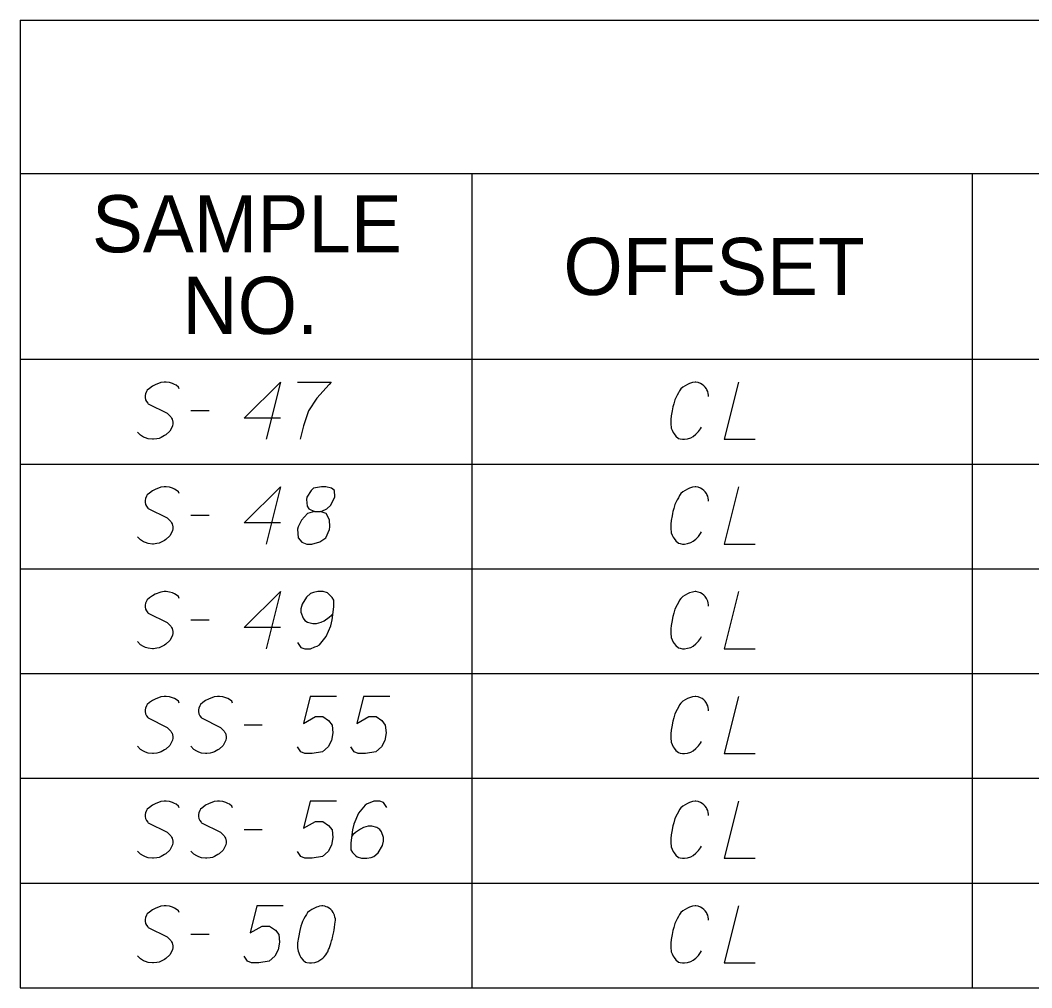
# Model space of a CAD drawing. Extents: x 2074207 to 2076812, y 516372 to 523312.
# Drawn here: x 2076260.6 to 2076345.6, y 517707.2 to 517788.5 of the extents above; entities that cross this region are included whole.
import ezdxf

# ---------------------------------------------------------------- set-up
doc = ezdxf.new("R2010")
doc.units = 0
for name, color, linetype in [('Prop DirtTable_ Soil Test Results - Outline (Major)', 7, 'Continuous'), ('Prop DirtTable_ Soil Test Results - Outline (Minor)', 7, 'Continuous'), ('Prop DirtTable_ Soil Test Results - Tx (Header - Small)', 7, 'Continuous'), ('Prop DirtTable_ Soil Test Results - Tx (Sample Data)', 7, 'Continuous')]:
    doc.layers.add(name, color=color, linetype=linetype)

msp = doc.modelspace()

# ---------------------------------------------------------------- linework, layer by layer
at = {"layer": 'Prop DirtTable_ Soil Test Results - Outline (Major)'}
for p, q in [((2076260.609, 517788.499), (2076260.609, 517760.014)), ((2076260.609, 517788.499), (2076811.903, 517788.499)), ((2076260.609, 517760.014), (2076260.609, 517751.214)), ((2076260.609, 517760.014), (2076811.903, 517760.014)), ((2076260.609, 517760.014), (2076811.903, 517760.014)), ((2076260.609, 517751.214), (2076260.609, 517742.414)), ((2076260.609, 517742.414), (2076260.609, 517733.614)), ((2076260.609, 517733.614), (2076260.609, 517724.814)), ((2076260.609, 517724.814), (2076260.609, 517716.014)), ((2076260.609, 517716.014), (2076260.609, 517707.214)), ((2076260.609, 517707.214), (2076811.903, 517707.214))]:
    msp.add_line(p, q, dxfattribs=at)
at = {"layer": 'Prop DirtTable_ Soil Test Results - Outline (Minor)'}
for p, q in [((2076260.609, 517775.614), (2076811.903, 517775.614)), ((2076298.545, 517775.614), (2076298.545, 517751.214)), ((2076340.594, 517775.614), (2076340.594, 517751.214)), ((2076260.609, 517751.214), (2076811.903, 517751.214)), ((2076260.609, 517751.214), (2076811.903, 517751.214)), ((2076298.546, 517751.214), (2076298.546, 517742.414)), ((2076340.594, 517751.214), (2076340.594, 517742.414)), ((2076260.609, 517742.414), (2076811.903, 517742.414)), ((2076260.609, 517742.414), (2076811.903, 517742.414)), ((2076298.546, 517742.414), (2076298.546, 517733.614)), ((2076340.594, 517742.414), (2076340.594, 517733.614)), ((2076260.609, 517733.614), (2076811.903, 517733.614)), ((2076260.609, 517733.614), (2076811.903, 517733.614)), ((2076298.546, 517733.614), (2076298.546, 517724.814)), ((2076340.594, 517733.614), (2076340.594, 517724.814)), ((2076260.609, 517724.814), (2076811.903, 517724.814)), ((2076260.609, 517724.814), (2076811.903, 517724.814)), ((2076298.546, 517724.814), (2076298.546, 517716.014)), ((2076340.594, 517724.814), (2076340.594, 517716.014)), ((2076260.609, 517716.014), (2076811.903, 517716.014)), ((2076260.609, 517716.014), (2076811.903, 517716.014)), ((2076298.546, 517716.014), (2076298.546, 517707.214)), ((2076340.594, 517716.014), (2076340.594, 517707.214)), ((2076260.609, 517707.214), (2076811.903, 517707.214))]:
    msp.add_line(p, q, dxfattribs=at)
at = {"layer": 'Prop DirtTable_ Soil Test Results - Tx (Sample Data)'}
for points in [[(2076273.968, 517757.528), (2076273.897, 517757.68), (2076273.721, 517757.831), (2076273.58, 517757.906), (2076273.403, 517757.982), (2076273.157, 517758.058), (2076272.874, 517758.095), (2076272.698, 517758.095), (2076272.416, 517758.058), (2076271.957, 517757.869), (2076271.71, 517757.755), (2076271.463, 517757.566), (2076271.287, 517757.415), (2076271.216, 517757.302), (2076271.146, 517757.113), (2076271.111, 517756.961), (2076271.111, 517756.81), (2076271.146, 517756.621), (2076271.216, 517756.47), (2076271.322, 517756.319), (2076271.358, 517756.281), (2076272.945, 517755.487), (2076273.262, 517755.185), (2076273.333, 517755.072), (2076273.368, 517754.996), (2076273.439, 517754.732), (2076273.439, 517754.58), (2076273.403, 517754.429), (2076273.333, 517754.24), (2076273.192, 517753.976), (2076272.839, 517753.673), (2076272.733, 517753.598), (2076272.451, 517753.446), (2076272.275, 517753.371), (2076272.098, 517753.333), (2076271.816, 517753.295), (2076271.71, 517753.295), (2076271.358, 517753.333), (2076271.146, 517753.409), (2076270.969, 517753.484), (2076270.723, 517753.635), (2076270.476, 517753.9)], [(2076282.469, 517755.072), (2076279.436, 517755.072), (2076282.469, 517758.095), (2076281.27, 517753.295)], [(2076283.916, 517758.095), (2076286.738, 517758.095), (2076286.561, 517757.906), (2076285.538, 517756.735), (2076284.833, 517755.676), (2076284.409, 517754.429), (2076284.127, 517753.295)], [(2076318.45, 517756.886), (2076318.45, 517756.999), (2076318.415, 517757.15), (2076318.38, 517757.302), (2076318.309, 517757.453), (2076318.274, 517757.528), (2076318.168, 517757.68), (2076318.062, 517757.793), (2076317.921, 517757.906), (2076317.78, 517757.982), (2076317.569, 517758.058), (2076317.392, 517758.095), (2076317.322, 517758.095), (2076317.11, 517758.058), (2076316.863, 517757.982), (2076316.687, 517757.906), (2076316.475, 517757.793), (2076316.299, 517757.68), (2076316.122, 517757.528), (2076316.016, 517757.377), (2076315.911, 517757.188), (2076315.805, 517756.999), (2076315.628, 517756.621), (2076315.523, 517756.281), (2076315.452, 517756.017), (2076315.417, 517755.865), (2076315.381, 517755.676), (2076315.311, 517755.261), (2076315.276, 517754.958), (2076315.276, 517754.618), (2076315.311, 517754.24), (2076315.381, 517754.051), (2076315.487, 517753.862), (2076315.558, 517753.749), (2076315.699, 517753.56), (2076315.911, 517753.371), (2076316.052, 517753.333), (2076316.263, 517753.295), (2076316.404, 517753.295), (2076316.44, 517753.295), (2076316.687, 517753.333), (2076316.969, 517753.409), (2076317.145, 517753.522), (2076317.392, 517753.711), (2076317.604, 517753.938), (2076317.78, 517754.165), (2076317.851, 517754.316)], [(2076320.955, 517758.095), (2076319.756, 517753.295), (2076322.366, 517753.295)], [(2076274.956, 517755.714), (2076276.472, 517755.714)], [(2076273.968, 517748.728), (2076273.897, 517748.88), (2076273.721, 517749.031), (2076273.58, 517749.106), (2076273.403, 517749.182), (2076273.157, 517749.258), (2076272.874, 517749.295), (2076272.698, 517749.295), (2076272.416, 517749.258), (2076271.957, 517749.069), (2076271.71, 517748.955), (2076271.463, 517748.766), (2076271.287, 517748.615), (2076271.216, 517748.502), (2076271.146, 517748.313), (2076271.111, 517748.161), (2076271.111, 517748.01), (2076271.146, 517747.821), (2076271.216, 517747.67), (2076271.322, 517747.519), (2076271.358, 517747.481), (2076272.945, 517746.687), (2076273.262, 517746.385), (2076273.333, 517746.272), (2076273.368, 517746.196), (2076273.439, 517745.932), (2076273.439, 517745.78), (2076273.403, 517745.629), (2076273.333, 517745.44), (2076273.192, 517745.176), (2076272.839, 517744.873), (2076272.733, 517744.798), (2076272.451, 517744.646), (2076272.275, 517744.571), (2076272.098, 517744.533), (2076271.816, 517744.495), (2076271.71, 517744.495), (2076271.358, 517744.533), (2076271.146, 517744.609), (2076270.969, 517744.684), (2076270.723, 517744.835), (2076270.476, 517745.1)], [(2076282.469, 517746.272), (2076279.436, 517746.272), (2076282.469, 517749.295), (2076281.27, 517744.495)], [(2076285.327, 517747.217), (2076285.82, 517747.217), (2076285.962, 517747.254), (2076286.385, 517747.443), (2076286.702, 517747.746), (2076287.055, 517748.464), (2076287.02, 517748.993), (2076286.773, 517749.182), (2076286.279, 517749.295), (2076285.926, 517749.295), (2076285.256, 517749.182), (2076285.044, 517748.993), (2076284.692, 517748.426), (2076284.656, 517748.237), (2076284.727, 517747.67), (2076284.868, 517747.443), (2076285.327, 517747.217), (2076284.762, 517747.065), (2076284.233, 517746.498), (2076283.951, 517745.932), (2076283.916, 517745.743), (2076283.951, 517745.024), (2076284.268, 517744.646), (2076284.692, 517744.495), (2076285.115, 517744.495), (2076285.785, 517744.684), (2076286.279, 517745.024), (2076286.597, 517745.705), (2076286.632, 517745.932), (2076286.597, 517746.536), (2076286.314, 517747.065), (2076285.82, 517747.217)], [(2076318.45, 517748.086), (2076318.45, 517748.199), (2076318.415, 517748.35), (2076318.38, 517748.502), (2076318.309, 517748.653), (2076318.274, 517748.728), (2076318.168, 517748.88), (2076318.062, 517748.993), (2076317.921, 517749.106), (2076317.78, 517749.182), (2076317.569, 517749.258), (2076317.392, 517749.295), (2076317.322, 517749.295), (2076317.11, 517749.258), (2076316.863, 517749.182), (2076316.687, 517749.106), (2076316.475, 517748.993), (2076316.299, 517748.88), (2076316.122, 517748.728), (2076316.016, 517748.577), (2076315.911, 517748.388), (2076315.805, 517748.199), (2076315.628, 517747.821), (2076315.523, 517747.481), (2076315.452, 517747.217), (2076315.417, 517747.065), (2076315.381, 517746.876), (2076315.311, 517746.461), (2076315.276, 517746.158), (2076315.276, 517745.818), (2076315.311, 517745.44), (2076315.381, 517745.251), (2076315.487, 517745.062), (2076315.558, 517744.949), (2076315.699, 517744.76), (2076315.911, 517744.571), (2076316.052, 517744.533), (2076316.263, 517744.495), (2076316.404, 517744.495), (2076316.44, 517744.495), (2076316.687, 517744.533), (2076316.969, 517744.609), (2076317.145, 517744.722), (2076317.392, 517744.911), (2076317.604, 517745.138), (2076317.78, 517745.365), (2076317.851, 517745.516)], [(2076320.955, 517749.295), (2076319.756, 517744.495), (2076322.366, 517744.495)], [(2076274.956, 517746.914), (2076276.472, 517746.914)], [(2076273.968, 517739.928), (2076273.897, 517740.08), (2076273.721, 517740.231), (2076273.58, 517740.306), (2076273.403, 517740.382), (2076273.157, 517740.458), (2076272.874, 517740.495), (2076272.698, 517740.495), (2076272.416, 517740.458), (2076271.957, 517740.269), (2076271.71, 517740.155), (2076271.463, 517739.966), (2076271.287, 517739.815), (2076271.216, 517739.702), (2076271.146, 517739.513), (2076271.111, 517739.361), (2076271.111, 517739.21), (2076271.146, 517739.021), (2076271.216, 517738.87), (2076271.322, 517738.719), (2076271.358, 517738.681), (2076272.945, 517737.887), (2076273.262, 517737.585), (2076273.333, 517737.472), (2076273.368, 517737.396), (2076273.439, 517737.132), (2076273.439, 517736.98), (2076273.403, 517736.829), (2076273.333, 517736.64), (2076273.192, 517736.376), (2076272.839, 517736.073), (2076272.733, 517735.998), (2076272.451, 517735.846), (2076272.275, 517735.771), (2076272.098, 517735.733), (2076271.816, 517735.695), (2076271.71, 517735.695), (2076271.358, 517735.733), (2076271.146, 517735.809), (2076270.969, 517735.884), (2076270.723, 517736.035), (2076270.476, 517736.3)], [(2076282.469, 517737.472), (2076279.436, 517737.472), (2076282.469, 517740.495), (2076281.27, 517735.695)], [(2076283.916, 517736.224), (2076284.198, 517735.809), (2076284.515, 517735.695), (2076285.009, 517735.695), (2076285.362, 517735.846), (2076285.574, 517735.922), (2076285.75, 517736.035), (2076286.314, 517736.716), (2076286.702, 517737.623), (2076286.808, 517738.114), (2076286.949, 517739.21), (2076286.949, 517739.777), (2076286.808, 517740.004), (2076286.526, 517740.306), (2076286.42, 517740.382), (2076286.067, 517740.495), (2076285.609, 517740.495), (2076285.256, 517740.42), (2076285.009, 517740.344), (2076284.656, 517740.042), (2076284.304, 517739.437), (2076284.198, 517739.059), (2076284.198, 517738.757), (2076284.374, 517738.265), (2076284.515, 517738.076), (2076284.762, 517737.925), (2076285.186, 517737.812), (2076285.503, 517737.812), (2076285.891, 517737.925), (2076286.138, 517738.039), (2076286.561, 517738.341), (2076286.773, 517738.53), (2076286.879, 517738.643)], [(2076318.45, 517739.286), (2076318.45, 517739.399), (2076318.415, 517739.55), (2076318.38, 517739.702), (2076318.309, 517739.853), (2076318.274, 517739.928), (2076318.168, 517740.08), (2076318.062, 517740.193), (2076317.921, 517740.306), (2076317.78, 517740.382), (2076317.569, 517740.458), (2076317.392, 517740.495), (2076317.322, 517740.495), (2076317.11, 517740.458), (2076316.863, 517740.382), (2076316.687, 517740.306), (2076316.475, 517740.193), (2076316.299, 517740.08), (2076316.122, 517739.928), (2076316.016, 517739.777), (2076315.911, 517739.588), (2076315.805, 517739.399), (2076315.628, 517739.021), (2076315.523, 517738.681), (2076315.452, 517738.417), (2076315.417, 517738.265), (2076315.381, 517738.076), (2076315.311, 517737.661), (2076315.276, 517737.358), (2076315.276, 517737.018), (2076315.311, 517736.64), (2076315.381, 517736.451), (2076315.487, 517736.262), (2076315.558, 517736.149), (2076315.699, 517735.96), (2076315.911, 517735.771), (2076316.052, 517735.733), (2076316.263, 517735.695), (2076316.404, 517735.695), (2076316.44, 517735.695), (2076316.687, 517735.733), (2076316.969, 517735.809), (2076317.145, 517735.922), (2076317.392, 517736.111), (2076317.604, 517736.338), (2076317.78, 517736.565), (2076317.851, 517736.716)], [(2076320.955, 517740.495), (2076319.756, 517735.695), (2076322.366, 517735.695)], [(2076274.956, 517738.114), (2076276.472, 517738.114)], [(2076273.968, 517731.128), (2076273.897, 517731.28), (2076273.721, 517731.431), (2076273.58, 517731.506), (2076273.403, 517731.582), (2076273.157, 517731.658), (2076272.874, 517731.695), (2076272.698, 517731.695), (2076272.416, 517731.658), (2076271.957, 517731.469), (2076271.71, 517731.355), (2076271.463, 517731.166), (2076271.287, 517731.015), (2076271.216, 517730.902), (2076271.146, 517730.713), (2076271.111, 517730.561), (2076271.111, 517730.41), (2076271.146, 517730.221), (2076271.216, 517730.07), (2076271.322, 517729.919), (2076271.358, 517729.881), (2076272.945, 517729.087), (2076273.262, 517728.785), (2076273.333, 517728.672), (2076273.368, 517728.596), (2076273.439, 517728.332), (2076273.439, 517728.18), (2076273.403, 517728.029), (2076273.333, 517727.84), (2076273.192, 517727.576), (2076272.839, 517727.273), (2076272.733, 517727.198), (2076272.451, 517727.046), (2076272.275, 517726.971), (2076272.098, 517726.933), (2076271.816, 517726.895), (2076271.71, 517726.895), (2076271.358, 517726.933), (2076271.146, 517727.009), (2076270.969, 517727.084), (2076270.723, 517727.235), (2076270.476, 517727.5)], [(2076278.448, 517731.128), (2076278.377, 517731.28), (2076278.201, 517731.431), (2076278.06, 517731.506), (2076277.883, 517731.582), (2076277.637, 517731.658), (2076277.354, 517731.695), (2076277.178, 517731.695), (2076276.896, 517731.658), (2076276.437, 517731.469), (2076276.19, 517731.355), (2076275.943, 517731.166), (2076275.767, 517731.015), (2076275.696, 517730.902), (2076275.626, 517730.713), (2076275.591, 517730.561), (2076275.591, 517730.41), (2076275.626, 517730.221), (2076275.696, 517730.07), (2076275.802, 517729.919), (2076275.838, 517729.881), (2076277.425, 517729.087), (2076277.742, 517728.785), (2076277.813, 517728.672), (2076277.848, 517728.596), (2076277.919, 517728.332), (2076277.919, 517728.18), (2076277.883, 517728.029), (2076277.813, 517727.84), (2076277.672, 517727.576), (2076277.319, 517727.273), (2076277.213, 517727.198), (2076276.931, 517727.046), (2076276.755, 517726.971), (2076276.578, 517726.933), (2076276.296, 517726.895), (2076276.19, 517726.895), (2076275.838, 517726.933), (2076275.626, 517727.009), (2076275.449, 517727.084), (2076275.203, 517727.235), (2076274.956, 517727.5)], [(2076287.196, 517731.695), (2076284.974, 517731.695), (2076284.409, 517729.428), (2076285.432, 517729.995), (2076286.032, 517729.995), (2076286.526, 517729.654), (2076286.808, 517729.276), (2076286.879, 517728.634), (2076286.773, 517727.991), (2076286.491, 517727.462), (2076285.997, 517727.046), (2076285.15, 517726.895), (2076284.515, 517726.895), (2076284.198, 517727.046), (2076283.916, 517727.462)], [(2076291.676, 517731.695), (2076289.454, 517731.695), (2076288.889, 517729.428), (2076289.912, 517729.995), (2076290.512, 517729.995), (2076291.006, 517729.654), (2076291.288, 517729.276), (2076291.359, 517728.634), (2076291.253, 517727.991), (2076290.971, 517727.462), (2076290.477, 517727.046), (2076289.63, 517726.895), (2076288.995, 517726.895), (2076288.678, 517727.046), (2076288.396, 517727.462)], [(2076318.45, 517730.486), (2076318.45, 517730.599), (2076318.415, 517730.75), (2076318.38, 517730.902), (2076318.309, 517731.053), (2076318.274, 517731.128), (2076318.168, 517731.28), (2076318.062, 517731.393), (2076317.921, 517731.506), (2076317.78, 517731.582), (2076317.569, 517731.658), (2076317.392, 517731.695), (2076317.322, 517731.695), (2076317.11, 517731.658), (2076316.863, 517731.582), (2076316.687, 517731.506), (2076316.475, 517731.393), (2076316.299, 517731.28), (2076316.122, 517731.128), (2076316.016, 517730.977), (2076315.911, 517730.788), (2076315.805, 517730.599), (2076315.628, 517730.221), (2076315.523, 517729.881), (2076315.452, 517729.617), (2076315.417, 517729.465), (2076315.381, 517729.276), (2076315.311, 517728.861), (2076315.276, 517728.558), (2076315.276, 517728.218), (2076315.311, 517727.84), (2076315.381, 517727.651), (2076315.487, 517727.462), (2076315.558, 517727.349), (2076315.699, 517727.16), (2076315.911, 517726.971), (2076316.052, 517726.933), (2076316.263, 517726.895), (2076316.404, 517726.895), (2076316.44, 517726.895), (2076316.687, 517726.933), (2076316.969, 517727.009), (2076317.145, 517727.122), (2076317.392, 517727.311), (2076317.604, 517727.538), (2076317.78, 517727.765), (2076317.851, 517727.916)], [(2076320.955, 517731.695), (2076319.756, 517726.895), (2076322.366, 517726.895)], [(2076279.436, 517729.314), (2076280.952, 517729.314)], [(2076273.968, 517722.328), (2076273.897, 517722.48), (2076273.721, 517722.631), (2076273.58, 517722.706), (2076273.403, 517722.782), (2076273.157, 517722.858), (2076272.874, 517722.895), (2076272.698, 517722.895), (2076272.416, 517722.858), (2076271.957, 517722.669), (2076271.71, 517722.555), (2076271.463, 517722.366), (2076271.287, 517722.215), (2076271.216, 517722.102), (2076271.146, 517721.913), (2076271.111, 517721.761), (2076271.111, 517721.61), (2076271.146, 517721.421), (2076271.216, 517721.27), (2076271.322, 517721.119), (2076271.358, 517721.081), (2076272.945, 517720.287), (2076273.262, 517719.985), (2076273.333, 517719.872), (2076273.368, 517719.796), (2076273.439, 517719.532), (2076273.439, 517719.38), (2076273.403, 517719.229), (2076273.333, 517719.04), (2076273.192, 517718.776), (2076272.839, 517718.473), (2076272.733, 517718.398), (2076272.451, 517718.246), (2076272.275, 517718.171), (2076272.098, 517718.133), (2076271.816, 517718.095), (2076271.71, 517718.095), (2076271.358, 517718.133), (2076271.146, 517718.209), (2076270.969, 517718.284), (2076270.723, 517718.435), (2076270.476, 517718.7)], [(2076278.448, 517722.328), (2076278.377, 517722.48), (2076278.201, 517722.631), (2076278.06, 517722.706), (2076277.883, 517722.782), (2076277.637, 517722.858), (2076277.354, 517722.895), (2076277.178, 517722.895), (2076276.896, 517722.858), (2076276.437, 517722.669), (2076276.19, 517722.555), (2076275.943, 517722.366), (2076275.767, 517722.215), (2076275.696, 517722.102), (2076275.626, 517721.913), (2076275.591, 517721.761), (2076275.591, 517721.61), (2076275.626, 517721.421), (2076275.696, 517721.27), (2076275.802, 517721.119), (2076275.838, 517721.081), (2076277.425, 517720.287), (2076277.742, 517719.985), (2076277.813, 517719.872), (2076277.848, 517719.796), (2076277.919, 517719.532), (2076277.919, 517719.38), (2076277.883, 517719.229), (2076277.813, 517719.04), (2076277.672, 517718.776), (2076277.319, 517718.473), (2076277.213, 517718.398), (2076276.931, 517718.246), (2076276.755, 517718.171), (2076276.578, 517718.133), (2076276.296, 517718.095), (2076276.19, 517718.095), (2076275.838, 517718.133), (2076275.626, 517718.209), (2076275.449, 517718.284), (2076275.203, 517718.435), (2076274.956, 517718.7)], [(2076287.196, 517722.895), (2076284.974, 517722.895), (2076284.409, 517720.628), (2076285.432, 517721.195), (2076286.032, 517721.195), (2076286.526, 517720.854), (2076286.808, 517720.476), (2076286.879, 517719.834), (2076286.773, 517719.191), (2076286.491, 517718.662), (2076285.997, 517718.246), (2076285.15, 517718.095), (2076284.515, 517718.095), (2076284.198, 517718.246), (2076283.916, 517718.662)], [(2076291.429, 517722.366), (2076291.147, 517722.782), (2076290.83, 517722.895), (2076290.336, 517722.895), (2076289.983, 517722.744), (2076289.771, 517722.669), (2076289.595, 517722.555), (2076289.031, 517721.875), (2076288.643, 517720.968), (2076288.537, 517720.476), (2076288.396, 517719.38), (2076288.396, 517718.813), (2076288.537, 517718.587), (2076288.819, 517718.284), (2076288.925, 517718.209), (2076289.278, 517718.095), (2076289.736, 517718.095), (2076290.089, 517718.171), (2076290.336, 517718.246), (2076290.689, 517718.549), (2076291.041, 517719.154), (2076291.147, 517719.532), (2076291.147, 517719.834), (2076290.971, 517720.325), (2076290.83, 517720.514), (2076290.583, 517720.665), (2076290.159, 517720.779), (2076289.842, 517720.779), (2076289.454, 517720.665), (2076289.207, 517720.552), (2076288.784, 517720.25), (2076288.572, 517720.061), (2076288.466, 517719.947)], [(2076318.45, 517721.686), (2076318.45, 517721.799), (2076318.415, 517721.95), (2076318.38, 517722.102), (2076318.309, 517722.253), (2076318.274, 517722.328), (2076318.168, 517722.48), (2076318.062, 517722.593), (2076317.921, 517722.706), (2076317.78, 517722.782), (2076317.569, 517722.858), (2076317.392, 517722.895), (2076317.322, 517722.895), (2076317.11, 517722.858), (2076316.863, 517722.782), (2076316.687, 517722.706), (2076316.475, 517722.593), (2076316.299, 517722.48), (2076316.122, 517722.328), (2076316.016, 517722.177), (2076315.911, 517721.988), (2076315.805, 517721.799), (2076315.628, 517721.421), (2076315.523, 517721.081), (2076315.452, 517720.817), (2076315.417, 517720.665), (2076315.381, 517720.476), (2076315.311, 517720.061), (2076315.276, 517719.758), (2076315.276, 517719.418), (2076315.311, 517719.04), (2076315.381, 517718.851), (2076315.487, 517718.662), (2076315.558, 517718.549), (2076315.699, 517718.36), (2076315.911, 517718.171), (2076316.052, 517718.133), (2076316.263, 517718.095), (2076316.404, 517718.095), (2076316.44, 517718.095), (2076316.687, 517718.133), (2076316.969, 517718.209), (2076317.145, 517718.322), (2076317.392, 517718.511), (2076317.604, 517718.738), (2076317.78, 517718.965), (2076317.851, 517719.116)], [(2076320.955, 517722.895), (2076319.756, 517718.095), (2076322.366, 517718.095)], [(2076279.436, 517720.514), (2076280.952, 517720.514)], [(2076273.968, 517713.528), (2076273.897, 517713.68), (2076273.721, 517713.831), (2076273.58, 517713.906), (2076273.403, 517713.982), (2076273.157, 517714.058), (2076272.874, 517714.095), (2076272.698, 517714.095), (2076272.416, 517714.058), (2076271.957, 517713.869), (2076271.71, 517713.755), (2076271.463, 517713.566), (2076271.287, 517713.415), (2076271.216, 517713.302), (2076271.146, 517713.113), (2076271.111, 517712.961), (2076271.111, 517712.81), (2076271.146, 517712.621), (2076271.216, 517712.47), (2076271.322, 517712.319), (2076271.358, 517712.281), (2076272.945, 517711.487), (2076273.262, 517711.185), (2076273.333, 517711.072), (2076273.368, 517710.996), (2076273.439, 517710.732), (2076273.439, 517710.58), (2076273.403, 517710.429), (2076273.333, 517710.24), (2076273.192, 517709.976), (2076272.839, 517709.673), (2076272.733, 517709.598), (2076272.451, 517709.446), (2076272.275, 517709.371), (2076272.098, 517709.333), (2076271.816, 517709.295), (2076271.71, 517709.295), (2076271.358, 517709.333), (2076271.146, 517709.409), (2076270.969, 517709.484), (2076270.723, 517709.635), (2076270.476, 517709.9)], [(2076282.716, 517714.095), (2076280.494, 517714.095), (2076279.929, 517711.828), (2076280.952, 517712.395), (2076281.552, 517712.395), (2076282.046, 517712.054), (2076282.328, 517711.676), (2076282.399, 517711.034), (2076282.293, 517710.391), (2076282.011, 517709.862), (2076281.517, 517709.446), (2076280.67, 517709.295), (2076280.035, 517709.295), (2076279.718, 517709.446), (2076279.436, 517709.862)], [(2076286.032, 517714.095), (2076285.962, 517714.095), (2076285.75, 517714.058), (2076285.609, 517714.02), (2076285.503, 517713.982), (2076285.327, 517713.906), (2076285.115, 517713.793), (2076284.939, 517713.68), (2076284.762, 517713.528), (2076284.656, 517713.377), (2076284.551, 517713.188), (2076284.445, 517712.999), (2076284.339, 517712.772), (2076284.268, 517712.621), (2076284.198, 517712.395), (2076284.092, 517712.017), (2076283.986, 517711.45), (2076283.916, 517710.996), (2076283.916, 517710.58), (2076283.951, 517710.278), (2076284.092, 517709.938), (2076284.198, 517709.749), (2076284.374, 517709.522), (2076284.586, 517709.371), (2076284.692, 517709.333), (2076284.903, 517709.295), (2076285.08, 517709.295), (2076285.362, 517709.333), (2076285.609, 517709.409), (2076285.785, 517709.522), (2076286.032, 517709.711), (2076286.138, 517709.824), (2076286.279, 517709.976), (2076286.385, 517710.127), (2076286.455, 517710.24), (2076286.526, 517710.429), (2076286.561, 517710.505), (2076286.632, 517710.694), (2076286.702, 517710.921), (2076286.773, 517711.147), (2076286.808, 517711.298), (2076286.843, 517711.412), (2076286.879, 517711.563), (2076286.949, 517711.903), (2076286.985, 517712.092), (2076287.02, 517712.281), (2076287.055, 517712.546), (2076287.09, 517712.886), (2076287.09, 517712.999), (2076287.055, 517713.15), (2076287.02, 517713.302), (2076286.914, 517713.528), (2076286.808, 517713.68), (2076286.702, 517713.793), (2076286.561, 517713.906), (2076286.42, 517713.982), (2076286.314, 517714.02), (2076286.209, 517714.058), (2076286.032, 517714.095)], [(2076318.45, 517712.886), (2076318.45, 517712.999), (2076318.415, 517713.15), (2076318.38, 517713.302), (2076318.309, 517713.453), (2076318.274, 517713.528), (2076318.168, 517713.68), (2076318.062, 517713.793), (2076317.921, 517713.906), (2076317.78, 517713.982), (2076317.569, 517714.058), (2076317.392, 517714.095), (2076317.322, 517714.095), (2076317.11, 517714.058), (2076316.863, 517713.982), (2076316.687, 517713.906), (2076316.475, 517713.793), (2076316.299, 517713.68), (2076316.122, 517713.528), (2076316.016, 517713.377), (2076315.911, 517713.188), (2076315.805, 517712.999), (2076315.628, 517712.621), (2076315.523, 517712.281), (2076315.452, 517712.017), (2076315.417, 517711.865), (2076315.381, 517711.676), (2076315.311, 517711.261), (2076315.276, 517710.958), (2076315.276, 517710.618), (2076315.311, 517710.24), (2076315.381, 517710.051), (2076315.487, 517709.862), (2076315.558, 517709.749), (2076315.699, 517709.56), (2076315.911, 517709.371), (2076316.052, 517709.333), (2076316.263, 517709.295), (2076316.404, 517709.295), (2076316.44, 517709.295), (2076316.687, 517709.333), (2076316.969, 517709.409), (2076317.145, 517709.522), (2076317.392, 517709.711), (2076317.604, 517709.938), (2076317.78, 517710.165), (2076317.851, 517710.316)], [(2076320.955, 517714.095), (2076319.756, 517709.295), (2076322.366, 517709.295)], [(2076274.956, 517711.714), (2076276.472, 517711.714)]]:
    msp.add_lwpolyline(points, dxfattribs=at)

# ---------------------------------------------------------------- texts
at = {"layer": 'Prop DirtTable_ Soil Test Results - Tx (Header - Small)'}
for s, p in [('SAMPLE', (2076266.632, 517769)), ('OFFSET', (2076306.254, 517765.414)), ('NO.', (2076274.244, 517762.143))]:
    msp.add_text(s, height=4.8, dxfattribs=at).set_placement(p)

doc.saveas('drawing.dxf')
